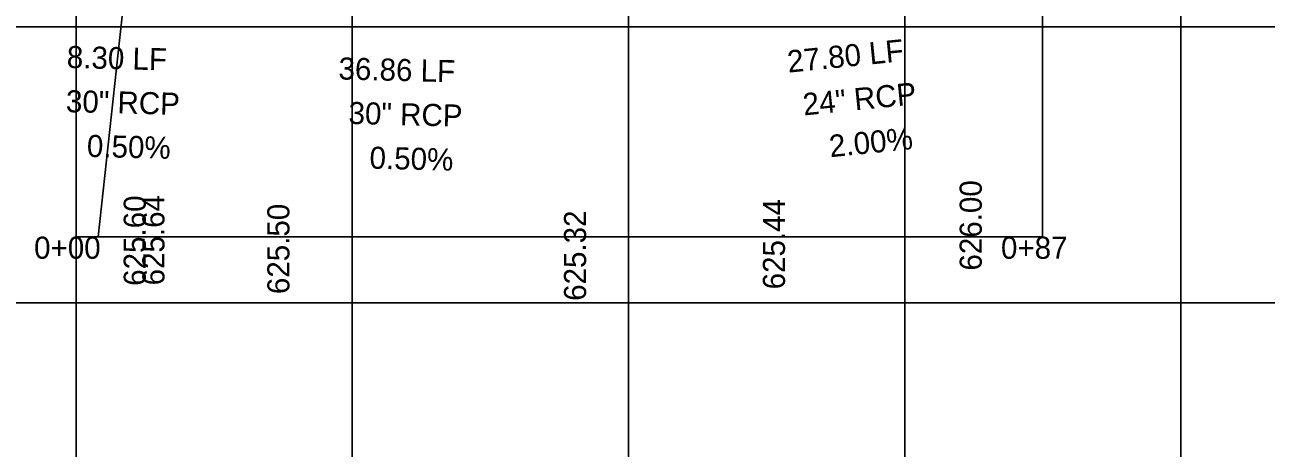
# Model space of a CAD drawing. Extents: x 2253035 to 2279930, y 13774972 to 13793443.
# Drawn here: x 2277794.8 to 2277907.1, y 13792678.1 to 13792716.5 of the extents above; entities that cross this region are included whole.
import ezdxf

# ---------------------------------------------------------------- set-up
doc = ezdxf.new("R2010")
doc.units = 0
for name, color, linetype in [('Default', 7, 'Continuous'), ('E_Utility_ATT_HH', 7, 'Continuous'), ('E_Utility_Telephone_Manhole Telephone_MHT_point', 7, 'Continuous'), ('E_Utillity_Water_Water Line_8in', 7, 'Continuous')]:
    doc.layers.add(name, color=color, linetype=linetype)

msp = doc.modelspace()

# ---------------------------------------------------------------- linework, layer by layer
at = {"layer": 'Default'}
msp.add_lwpolyline([(2277799.4, 13792697.27), (2277799.4, 13792791.27), (2277886.87, 13792791.27), (2277886.87, 13792697.27)], close=True, dxfattribs=at)
at = {"layer": 'E_Utility_Telephone_Manhole Telephone_MHT_point'}
for p, q in [((2277799.4, 13792491.27), (2277799.4, 13792791.27)), ((2277824.4, 13792491.27), (2277824.4, 13792791.27)), ((2277849.4, 13792491.27), (2277849.4, 13792791.27)), ((2277874.4, 13792491.27), (2277874.4, 13792791.27)), ((2277899.4, 13792491.27), (2277899.4, 13792791.27)), ((2277749.4, 13792716.27), (2278074.4, 13792716.27)), ((2277749.4, 13792691.27), (2278074.4, 13792691.27))]:
    msp.add_line(p, q, dxfattribs=at)
at = {"layer": 'E_Utillity_Water_Water Line_8in'}
msp.add_lwpolyline([(2277799.4, 13792697.27), (2277801.4, 13792697.27), (2277801.4, 13792697.27), (2277806.82, 13792747.27)], dxfattribs=at)

# ---------------------------------------------------------------- texts
at = {"layer": 'Default'}
for s, p in [('0+00', (2277795.6, 13792695.27)), ('0+87', (2277883.11, 13792695.27))]:
    msp.add_text(s, height=2, dxfattribs=at).set_placement(p)
at = {"layer": 'E_Utility_ATT_HH'}
for s, rotation, p in [('27.80 LF', 5.7106, (2277863.87, 13792712.12)), ('8.30 LF', 358.5679, (2277798.54, 13792712.55)), ('36.86 LF', 358.5679, (2277823.13, 13792711.51)), ('24" RCP', 5.7106, (2277865.27, 13792708.24)), ('30" RCP', 358.5679, (2277798.46, 13792708.55)), ('30" RCP', 358.5679, (2277824.04, 13792707.48)), ('0.50%', 358.5679, (2277800.36, 13792704.5)), ('2.00%', 5.7106, (2277867.66, 13792704.46)), ('0.50%', 358.5679, (2277825.94, 13792703.43)), ('626.00', 90, (2277881.37, 13792694.2)), ('625.60', 90, (2277805.71, 13792692.82)), ('625.64', 90, (2277807.4, 13792692.86)), ('625.44', 90, (2277863.56, 13792692.5)), ('625.50', 90, (2277818.71, 13792692.07)), ('625.32', 90, (2277845.56, 13792691.46))]:
    msp.add_text(s, height=2, rotation=rotation, dxfattribs=at).set_placement(p)

doc.saveas('drawing.dxf')
